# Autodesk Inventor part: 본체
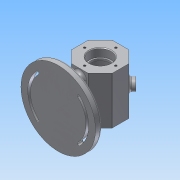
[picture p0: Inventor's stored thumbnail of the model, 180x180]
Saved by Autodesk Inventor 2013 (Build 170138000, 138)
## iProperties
Created: 2017-06
Part Number: 본체
Material: 알루미늄 6061
Document SubType Name: Modeling
Designer: Administrator
Density: 2.71 g/cm^3
Mass: 562.565 g
Surface Area: 565.689 cm^2
Volume: 207.589 cm^3
Author: Administrator
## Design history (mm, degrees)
node "작업 평면1"
sketch "스케치2"
  geometry: C1 r 55 at (0, 0); 1 further point
  constraints: 1 centre point, 1 coincident
  dimensions: "d4" = 110 diameter of C1
extrude "돌출2" join sketch "스케치2" distance "d5" = 10; taper "d6" = 0 deg
sketch "스케치3"
  geometry: L1 (-24, 29)-(-52, 29); L2 (-52, 29)-(-52, -29); L3 (-52, -29)-(-24, -29); L4 (-24, -29)-(-24, 29); L5 (-52, -55)-(-52, 55) reference; 1 further point
  constraints: 8 end point, 2 parallel, 1 collinear, 1 horizontal, 1 perpendicular
  dimensions: "d8" = 58 distance of L1.end L2.end; "d10" = 29 distance from line of point (0, 0) L1; "d11" = 24 distance from line of point (0, 0) L4
extrude "돌출3" join sketch "스케치3" stored distance "d12" = 10; taper "d13" = 0 deg
sketch "스케치5"
  geometry: L1 (-12.426, 30)-(12.426, 30); L2 (12.426, 30)-(30, 12.426); L3 (30, 12.426)-(30, -12.426); L4 (30, -12.426)-(12.426, -30); L5 (12.426, -30)-(-12.426, -30); L6 (-12.426, -30)-(-30, -12.426); L7 (-30, -12.426)-(-30, 12.426); L8 (-30, 12.426)-(-12.426, 30); 2 further points
  constraints: 16 end point, 1 coincident, 1 horizontal, 17 other
  dimensions: "d18" = 60 distance between parallel lines of L5 L1
extrude "돌출5" join sketch "스케치5" stored distance "d19" = 70; taper "d20" = 0 deg
sketch "스케치6"
  geometry: C1 r 8 at (-12.426, 35); 1 further point
  constraints: 1 centre point, 1 coincident
  dimensions: "d21" = 16 diameter of C1
extrude "돌출6" join sketch "스케치6" distance "d22" = 7; taper "d23" = 0 deg
sketch "스케치7"
  geometry: L1 (0, 0)-(-43, 43); L2 (0, 0)-(60.811, 0); L3 (0, 0)-(-44.214, -44.214); C1 r 55 at (0, 0) reference; A1 r 48 centre (0, 0) between (-33.941, 33.941) and (-33.941, -33.941); A2 r 5 centre (-30.406, 30.406) between (-26.87, 26.87) and (-33.941, 33.941); A3 r 5 centre (-30.406, -30.406) between (-33.941, -33.941) and (-26.87, -26.87); A4 r 38 centre (0, 0) between (-26.87, 26.87) and (-26.87, -26.87); A5 r 2 centre (-30.406, -30.406) between (-31.82, -31.82) and (-28.991, -28.991); A6 r 2 centre (-30.406, 30.406) between (-28.991, 28.991) and (-31.82, 31.82); A7 r 45 centre (0, 0) between (-31.82, 31.82) and (-31.82, -31.82); A8 r 41 centre (0, 0) between (-28.991, 28.991) and (-28.991, -28.991)
  constraints: 16 point on circle, 8 centre point, 7 coincident, 6 end point, 4 point on line, 1 equal length, 1 horizontal
  dimensions: "d24" = 96 diameter of A1; "d26" = 135 deg angle of L2 L1; "d27" = 90 deg angle of L1 L3; "d28" = 76 diameter of A4; "d29" = 10 diameter of A3; "d30" = 10 diameter of A2; "d31" = 4 diameter of A5; "d32" = 4 diameter of A6; "d33" = 82 diameter of A8; "d34" = 90 diameter of A7
extrude "돌출7" cut sketch "스케치7" distance "d35" = 3; taper "d36" = 0 deg
extrude "돌출8" cut sketch "스케치7" stored distance "d37" = 3; taper "d38" = 0 deg
sketch "스케치8"
  geometry: 2 further points
  constraints: 1 coincident
hole "구멍1" sketch "스케치8" at (0, 0) diameter "d39" = 28; stored, may be unused: countersink angle "d43" = 90 deg, drill point angle "d45" = 0 deg; dims "d40" = 6, "d41" = 32, "d42" = 12, "d44" = 8
sketch "스케치9"
  geometry: L1 (25, 20)-(0, 20); L2 (0, 20)-(0, -20); L3 (0, -20)-(25, -20); L4 (25, -20)-(25, 20); 2 further points
  constraints: 8 end point, 2 parallel, 1 coincident, 1 horizontal, 1 midpoint, 1 perpendicular
  dimensions: "d46" = 40 distance of L3.end L1.start; "d48" = 25 distance of L2.end L3.end
revolve "회전1" sketch "스케치9" stored, may be unused: angle "d49" = 90 deg
hole "구멍2" diameter "d52" = 28; stored, may be unused: countersink angle "d56" = 90 deg, drill point angle "d58" = 0 deg; dims "d50" = 10, "d51" = 10, "d53" = 6, "d54" = 32, "d55" = 12, "d57" = 8
chamfer "모따기1" distance "d59" = 1; stored, may be unused: second distance "d60" = 2, angle "d61" = 45 deg
fillet "모깎기1" dims "d62" = 0.3
sketch "스케치10"
  geometry: C1 r 17 at (0, 0) reference; 1 further point
  constraints: 1 vertical alignment
  dimensions: "d63" = 23 distance of C1.centre point (0, 23)
hole "구멍3" sketch "스케치10" at (0, 23) diameter "d64" = 3.242; stored, may be unused: countersink angle "d68" = 90 deg, drill point angle "d70" = 118 deg; dims "d65" = 8, "d66" = 32, "d67" = 12, "d69" = 10
hole "구멍4" diameter "d76" = 8; stored, may be unused: countersink angle "d80" = 90 deg, drill point angle "d82" = 118 deg; dims "d74" = 10, "d75" = 10, "d77" = 8, "d78" = 32, "d79" = 12, "d81" = 15
fillet "모깎기2" dims "d83" = 3
sketch "스케치11"
  geometry: L1 (0, 0)-(-17.574, 0) reference; L2 (-17.574, 0)-(-17.574, 70) reference; 2 further points
  constraints: 1 other
  dimensions: "d84" = 35 distance from line of L1 point (12.426, 35); "d85" = 30 distance from line of point (12.426, 35) L2
feature "엠보싱1" sketch "스케치11" dims "d18" = 60, "d86" = 0.5, "d87" = 0
fillet "모깎기3" dims "d88" = 5
fillet "모깎기4" dims "d89" = 5
fillet "모깎기5" dims "d90" = 3
fillet "모깎기6" dims "d91" = 1
fillet "모깎기7" dims "d92" = 3
chamfer "모따기2" distance "d93" = 1; stored, may be unused: second distance "d94" = 2, angle "d95" = 45 deg
node "솔리드1"
mirror "대칭1"
pattern_circular "원형 패턴1" dims angle "d72" = 360 deg
mirror "대칭2"
other parameters: "d3" = -62, "d25" = 86
